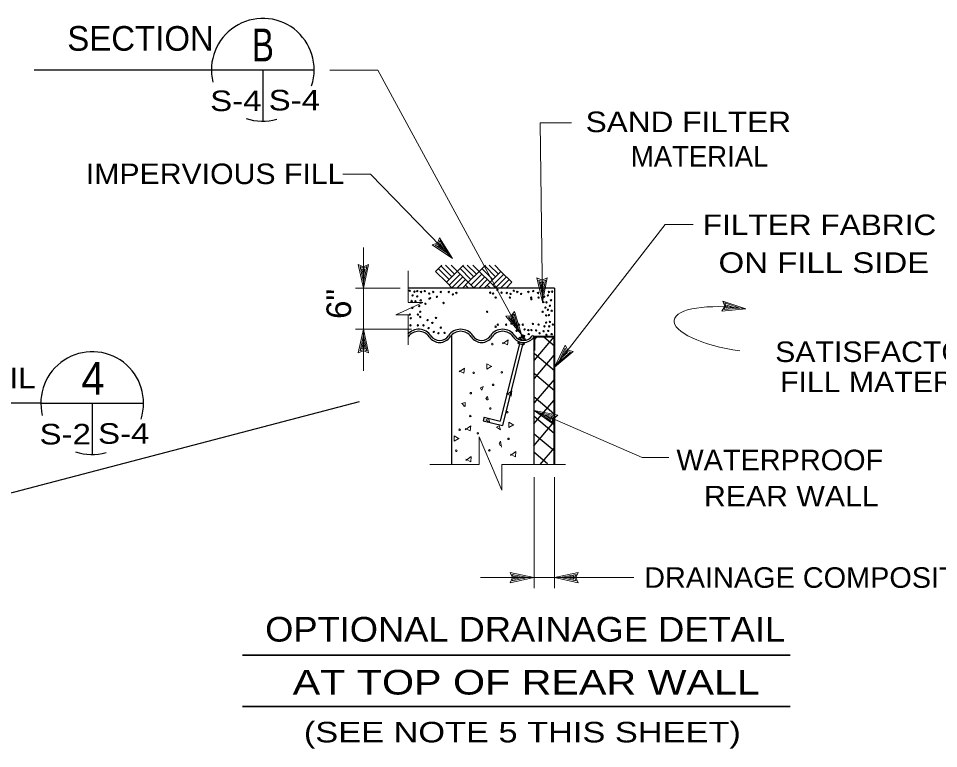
# Model space of a CAD drawing. Extents: x -22.3 to 19.7, y -11.8 to 18.2.
# Drawn here: x -0.15 to 5.45, y -4.4 to 0.04 of the extents above; entities that cross this region are included whole.
import ezdxf
from ezdxf.enums import TextEntityAlignment as Align

# ---------------------------------------------------------------- set-up
doc = ezdxf.new("R2010")
doc.units = 0
doc.header["$LTSCALE"] = 0.05
doc.layers.add('1', color=7, linetype='Continuous', lineweight=13)
doc.layers.add('2', color=7, linetype='Continuous', lineweight=13)

msp = doc.modelspace()

# ---------------------------------------------------------------- linework, layer by layer
at = {"layer": '1'}
for p, q in [((1.74658, -0.26969), (2.03958, -0.26969)), ((2.03958, -0.26969), (2.91358, -1.87769)), ((3.02658, -0.58969), (3.21858, -0.58969)), ((3.02658, -0.58969), (3.04058, -1.67769)), ((1.82558, -0.90269), (1.99558, -0.90269)), ((1.99558, -0.90269), (2.49358, -1.41469)), ((3.78758, -1.20869), (3.11458, -2.07569)), ((3.78758, -1.20869), (3.95858, -1.20869)), ((2.49358, -1.41469), (2.37058, -1.33269)), ((2.38758, -1.33469), (2.40858, -1.32769)), ((2.46758, -1.38769), (2.38758, -1.33469)), ((2.40458, -1.33669), (2.41458, -1.33269)), ((2.44258, -1.36269), (2.40458, -1.33669)), ((2.40858, -1.32769), (2.41658, -1.30669)), ((2.41458, -1.33269), (2.41758, -1.32369)), ((2.49358, -1.41469), (2.41558, -1.28969)), ((2.46758, -1.38769), (2.41658, -1.30669)), ((2.44258, -1.36269), (2.41758, -1.32369)), ((1.95158, -1.59569), (1.92058, -1.45169)), ((1.95158, -1.59569), (1.98258, -1.45169)), ((2.42858, -1.45469), (2.39058, -1.49369)), ((2.45158, -1.45469), (2.50658, -1.50969)), ((2.56158, -1.45469), (2.52258, -1.49369)), ((2.58358, -1.45469), (2.63958, -1.50969)), ((2.61758, -1.45469), (2.65658, -1.49369)), ((2.69458, -1.45469), (2.65658, -1.49369)), ((2.71758, -1.45469), (2.77258, -1.50969)), ((1.95158, -1.55869), (1.93158, -1.46469)), ((1.93158, -1.46469), (1.95158, -1.47369)), ((1.95158, -1.52269), (1.94158, -1.47769)), ((1.94158, -1.47769), (1.95158, -1.48169)), ((1.95158, -1.55869), (1.97158, -1.46469)), ((1.95158, -1.47369), (1.97158, -1.46469)), ((1.95158, -1.52269), (1.96058, -1.47769)), ((1.95158, -1.48169), (1.96058, -1.47769)), ((2.22458, -1.67969), (2.22458, -1.49069)), ((2.39058, -1.49369), (2.45658, -1.55969)), ((2.40658, -1.47669), (2.47358, -1.54269)), ((2.42358, -1.46069), (2.48958, -1.52669)), ((2.52258, -1.49369), (2.45658, -1.55969)), ((2.53958, -1.50969), (2.47358, -1.57669)), ((2.53958, -1.47669), (2.60558, -1.54269)), ((2.55558, -1.46069), (2.62258, -1.52669)), ((2.65658, -1.49369), (2.58958, -1.55969)), ((2.67258, -1.50969), (2.60558, -1.57669)), ((2.65658, -1.49369), (2.72258, -1.55969)), ((2.67258, -1.47669), (2.73858, -1.54269)), ((2.68958, -1.46069), (2.75558, -1.52669)), ((2.78858, -1.49369), (2.72258, -1.55969)), ((2.80558, -1.50969), (2.73858, -1.57669)), ((2.45658, -1.55969), (2.49258, -1.59569)), ((2.55558, -1.52669), (2.48958, -1.59269)), ((2.57258, -1.54269), (2.52058, -1.59569)), ((2.58958, -1.55969), (2.55358, -1.59569)), ((2.58958, -1.55969), (2.62558, -1.59569)), ((2.68958, -1.52669), (2.62258, -1.59269)), ((2.70558, -1.54269), (2.65358, -1.59569)), ((2.72258, -1.55969), (2.68658, -1.59569)), ((2.72258, -1.55969), (2.68658, -1.59569)), ((2.72258, -1.55969), (2.75758, -1.59569)), ((2.82158, -1.52669), (2.75558, -1.59269)), ((2.83858, -1.54269), (2.78658, -1.59569)), ((2.85458, -1.55969), (2.81958, -1.59569)), ((3.04058, -1.67769), (3.00758, -1.53369)), ((3.04058, -1.64069), (3.01858, -1.54669)), ((3.01858, -1.54669), (3.03858, -1.55569)), ((3.03958, -1.60469), (3.02858, -1.55969)), ((3.02858, -1.55969), (3.03958, -1.56369)), ((3.03858, -1.55569), (3.05858, -1.54669)), ((3.03958, -1.60469), (3.04758, -1.55969)), ((3.03958, -1.56369), (3.04758, -1.55969)), ((3.04058, -1.67769), (3.06958, -1.53369)), ((3.04058, -1.64069), (3.05858, -1.54669)), ((2.17458, -1.59569), (1.90358, -1.59569)), ((2.55558, -1.59269), (2.55858, -1.59569)), ((2.57258, -1.57669), (2.59158, -1.59569)), ((2.68958, -1.59269), (2.69158, -1.59569)), ((2.70558, -1.57669), (2.72458, -1.59569)), ((4.27858, -1.72069), (4.13858, -1.67369)), ((2.14858, -1.75669), (2.31358, -1.68169)), ((2.22458, -1.68169), (2.31358, -1.68169)), ((4.27858, -1.72069), (4.13158, -1.73569)), ((4.14658, -1.72569), (4.15758, -1.70669)), ((4.24158, -1.71669), (4.14658, -1.72569)), ((4.24158, -1.71669), (4.15058, -1.68569)), ((4.15758, -1.70669), (4.15058, -1.68569)), ((4.16058, -1.71769), (4.16558, -1.70769)), ((4.20558, -1.71269), (4.16058, -1.71769)), ((4.20558, -1.71269), (4.16258, -1.69869)), ((4.16558, -1.70769), (4.16258, -1.69869)), ((2.14858, -1.75669), (2.22458, -1.75669)), ((2.22458, -1.93969), (2.22458, -1.75669)), ((2.91358, -1.87769), (2.81758, -1.76569)), ((2.83358, -1.77169), (2.85558, -1.77069)), ((2.89558, -1.84469), (2.83358, -1.77169)), ((2.84858, -1.77869), (2.85958, -1.77769)), ((2.87858, -1.81369), (2.84858, -1.77869)), ((2.85558, -1.77069), (2.86858, -1.75269)), ((2.85958, -1.77769), (2.86558, -1.76969)), ((2.87858, -1.81369), (2.86558, -1.76969)), ((2.89558, -1.84469), (2.86858, -1.75269)), ((2.91358, -1.87769), (2.87158, -1.73669)), ((2.24458, -1.84569), (1.90358, -1.84569)), ((1.95158, -1.84569), (1.92058, -1.98969)), ((1.95158, -1.84569), (1.95158, -2.09769)), ((1.95158, -1.84569), (1.98258, -1.98969)), ((1.95158, -1.88269), (1.93158, -1.97669)), ((1.95158, -1.88269), (1.97158, -1.97669)), ((1.95158, -1.91869), (1.94258, -1.96369)), ((1.95158, -1.91869), (1.96158, -1.96369)), ((3.11458, -2.07569), (3.17858, -1.94269)), ((1.95158, -1.96769), (1.93158, -1.97669)), ((1.95158, -1.95969), (1.94258, -1.96369)), ((1.96158, -1.96369), (1.95158, -1.95969)), ((1.97158, -1.97669), (1.95158, -1.96769)), ((3.11458, -2.07569), (3.22758, -1.98069)), ((3.13758, -2.04669), (3.17958, -1.95969)), ((3.13758, -2.04669), (3.21058, -1.98469)), ((3.15958, -2.01769), (3.17858, -1.97669)), ((3.15958, -2.01769), (3.19358, -1.98769)), ((3.17858, -1.97669), (3.18458, -1.98569)), ((3.17958, -1.95969), (3.18958, -1.97969)), ((3.18458, -1.98569), (3.19358, -1.98769)), ((3.18958, -1.97969), (3.21058, -1.98469)), ((3.64658, -2.62469), (2.98958, -2.33869)), ((2.98958, -2.33869), (3.13358, -2.36769)), ((2.98958, -2.33869), (3.10958, -2.42469)), ((3.02358, -2.35369), (3.11758, -2.37269)), ((3.02358, -2.35369), (3.10158, -2.40969)), ((3.05658, -2.36769), (3.09458, -2.39369)), ((3.05658, -2.36769), (3.10158, -2.37669)), ((3.10158, -2.37669), (3.09458, -2.38469)), ((3.09458, -2.38469), (3.09458, -2.39369)), ((3.11758, -2.37269), (3.10158, -2.38769)), ((3.10158, -2.38769), (3.10158, -2.40969)), ((2.65658, -2.66769), (2.65658, -2.49969)), ((2.79358, -2.82469), (2.65658, -2.49969)), ((3.64658, -2.62469), (3.80958, -2.62469)), ((2.65658, -2.66769), (2.35658, -2.66769)), ((2.79358, -2.82469), (2.79358, -2.66769)), ((3.18058, -2.66769), (2.79358, -2.66769)), ((2.98958, -2.74469), (2.98958, -3.41969)), ((3.11458, -2.74469), (3.11458, -3.41969)), ((2.98858, -3.35569), (2.84458, -3.32469)), ((2.98858, -3.35569), (2.84458, -3.38669)), ((2.95158, -3.35569), (2.85758, -3.33569)), ((2.86658, -3.35569), (2.85758, -3.33569)), ((2.95158, -3.35569), (2.85758, -3.37569)), ((2.85758, -3.37569), (2.86658, -3.35569)), ((2.91558, -3.35569), (2.87058, -3.34669)), ((2.87458, -3.35569), (2.87058, -3.34669)), ((2.91558, -3.35569), (2.87058, -3.36569)), ((2.87058, -3.36569), (2.87458, -3.35569)), ((3.11458, -3.35569), (3.25858, -3.32469)), ((3.11458, -3.35569), (3.59658, -3.35569)), ((3.11458, -3.35569), (3.25858, -3.38669)), ((3.15158, -3.35569), (3.24558, -3.33569)), ((3.15158, -3.35569), (3.24558, -3.37569)), ((3.18758, -3.35569), (3.23258, -3.34569)), ((3.18758, -3.35569), (3.23258, -3.36469)), ((3.23258, -3.34569), (3.22858, -3.35569)), ((3.22858, -3.35569), (3.23258, -3.36469)), ((3.24558, -3.33569), (3.23658, -3.35569)), ((3.23658, -3.35569), (3.24558, -3.37569))]:
    msp.add_line(p, q, dxfattribs=at)
at = {"layer": '1', "lineweight": 25}
for p, q in [((3.11458, -1.59569), (2.22458, -1.59569)), ((3.11458, -1.59569), (3.11458, -1.89169)), ((2.48958, -2.66769), (2.48958, -1.88169)), ((2.89958, -1.89369), (2.89758, -1.90369)), ((2.89958, -1.89369), (2.93658, -1.90269)), ((2.90758, -1.89669), (2.90558, -1.90569)), ((2.91358, -1.87769), (2.90958, -1.89669)), ((2.90958, -1.89369), (2.92858, -1.89869)), ((2.91058, -1.89069), (2.92958, -1.89569)), ((2.91158, -1.88369), (2.93058, -1.88869)), ((2.91158, -1.88669), (2.93058, -1.89169)), ((2.91258, -1.87969), (2.93158, -1.88469)), ((2.91358, -1.87769), (2.93258, -1.88269)), ((2.92958, -1.90069), (2.92758, -1.90969)), ((2.93258, -1.88269), (2.92858, -1.90069)), ((2.93658, -1.90269), (2.93458, -1.91269)), ((2.98958, -1.89169), (2.97958, -1.88369)), ((2.98858, -1.91469), (3.00658, -1.89369)), ((2.98958, -2.66769), (2.98958, -1.89169)), ((2.99158, -2.03369), (3.11258, -1.89069)), ((3.11458, -1.94869), (3.04858, -1.89269)), ((2.90058, -1.93269), (2.78458, -2.40469)), ((2.91958, -1.93769), (2.79858, -2.43069)), ((2.89358, -1.91969), (2.89058, -1.93069)), ((2.89058, -1.93069), (2.92758, -1.93969)), ((2.89358, -1.91969), (2.93058, -1.92869)), ((2.89758, -1.90369), (2.93458, -1.91269)), ((2.90058, -1.92169), (2.89758, -1.93169)), ((2.92358, -1.92869), (2.92158, -1.93869)), ((2.93058, -1.92869), (2.92758, -1.93969)), ((2.99158, -2.14569), (3.11258, -2.00269)), ((3.11458, -2.09769), (2.99258, -1.99469)), ((3.11458, -2.21969), (2.99258, -2.11669)), ((2.99258, -2.29369), (3.11358, -2.15069)), ((-0.01042, -2.29469), (-2.00442, -2.29469)), ((3.11058, -2.35969), (2.98858, -2.25669)), ((2.98858, -2.42069), (3.10958, -2.27769)), ((2.68558, -2.38069), (2.68058, -2.40169)), ((2.68058, -2.40169), (2.79858, -2.43069)), ((2.68558, -2.38069), (2.78458, -2.40469)), ((3.11258, -2.47869), (2.99058, -2.37569)), ((2.98858, -2.55369), (3.10958, -2.41069)), ((3.11258, -2.58569), (2.99058, -2.48269)), ((3.02758, -2.66769), (3.11358, -2.56569)), ((3.07258, -2.66469), (2.98858, -2.59369))]:
    msp.add_line(p, q, dxfattribs=at)
at = {"layer": '1', "lineweight": 40}
msp.add_line((3.11458, -2.66769), (3.11458, -1.89169), dxfattribs=at)
at = {"layer": '1', "lineweight": 35}
for p, q in [((1.21658, -3.82769), (4.54758, -3.82769)), ((1.21658, -4.13869), (4.54758, -4.13869))]:
    msp.add_line(p, q, dxfattribs=at)
at = {"layer": '1'}
for points in [[(2.37058, -1.33269), (2.40258, -1.32169), (2.41558, -1.28969)], [(1.95158, -1.84569), (1.95158, -1.59569), (1.95158, -1.34769)], [(1.92058, -1.45169), (1.95158, -1.46569), (1.98258, -1.45169)], [(2.48458, -1.45469), (2.58958, -1.55969), (2.55358, -1.59569)], [(2.75058, -1.45469), (2.78858, -1.49369), (2.85458, -1.55969)], [(3.00758, -1.53369), (3.03858, -1.54769), (3.06958, -1.53369)], [(4.13158, -1.73569), (4.14958, -1.70569), (4.13858, -1.67369)], [(2.81758, -1.76569), (2.85158, -1.76369), (2.87158, -1.73669)], [(3.17858, -1.94269), (3.19458, -1.97269), (3.22758, -1.98069)], [(1.98258, -1.98969), (1.95158, -1.97569), (1.92058, -1.98969)], [(3.13358, -2.36769), (3.10858, -2.39069), (3.10958, -2.42469)], [(3.11458, -3.35569), (2.98858, -3.35569), (2.66358, -3.35569)], [(2.84458, -3.38669), (2.85858, -3.35569), (2.84458, -3.32469)], [(3.25858, -3.32469), (3.24458, -3.35569), (3.25858, -3.38669)]]:
    msp.add_lwpolyline(points, dxfattribs=at)
at = {"layer": '1', "lineweight": 40}
msp.add_lwpolyline([(3.11458, -1.89169), (2.98958, -1.89169), (2.98958, -1.97469)], dxfattribs=at)
at = {"layer": '1', "lineweight": 25}
msp.add_lwpolyline([(1.92558, -2.28769), (-3.54042, -3.71869), (-3.27742, -3.58569)], dxfattribs=at)
at = {"layer": '1'}
for centre in [(2.23408, -1.61169), (2.26208, -1.61669), (2.27908, -1.61369), (2.30208, -1.61869), (2.32508, -1.61369), (2.37608, -1.61869), (2.42208, -1.61869), (2.47108, -1.61869), (2.51708, -1.62469), (2.72208, -1.62269), (2.76708, -1.60569), (2.79208, -1.62269), (2.82408, -1.62469), (2.86608, -1.61169), (2.88808, -1.61869), (2.95508, -1.61869), (2.98508, -1.61369), (3.01408, -1.62469), (3.04208, -1.61169), (3.08008, -1.61869), (3.09908, -1.61669), (2.24508, -1.67369), (2.25108, -1.63969), (2.26808, -1.67569), (2.27908, -1.64569), (2.30008, -1.66969), (2.35208, -1.62869), (2.35308, -1.65869), (2.35708, -1.65669), (2.39908, -1.64769), (2.49608, -1.63369), (2.74008, -1.62869), (2.75608, -1.65269), (2.84308, -1.65269), (2.84708, -1.63069), (2.91108, -1.63069), (2.97208, -1.65269), (2.97408, -1.66269), (3.01708, -1.65269), (3.04608, -1.67969), (3.05208, -1.64769), (3.06508, -1.68169), (3.07408, -1.63969), (3.09308, -1.66869), (2.24908, -1.71569), (2.29108, -1.70469), (2.29708, -1.73869), (2.32908, -1.69069), (2.43908, -1.68569), (2.70408, -1.73869), (3.04208, -1.73869), (3.05908, -1.71369), (3.07408, -1.72669), (3.08608, -1.70269), (3.09708, -1.73269), (2.23408, -1.75569), (2.24008, -1.77869), (2.28308, -1.75569), (2.29708, -1.77069), (2.34208, -1.78969), (2.39308, -1.77669), (3.06308, -1.76169), (3.08008, -1.75969), (2.23808, -1.82169), (2.28308, -1.82169), (2.31708, -1.82169), (2.34808, -1.83869), (2.37108, -1.80669), (2.42208, -1.83569), (2.75608, -1.82969), (2.76908, -1.81769), (2.82008, -1.81769), (2.85208, -1.81069), (2.87708, -1.81069), (2.88308, -1.82969), (2.89808, -1.81769), (2.92108, -1.81769), (2.93208, -1.84669), (2.95508, -1.85069), (2.97408, -1.85069), (2.98308, -1.81269), (3.01708, -1.81669), (3.05308, -1.82769), (3.06308, -1.80469), (3.08208, -1.82769), (3.08608, -1.80069), (3.10508, -1.81669), (2.38008, -1.86169), (2.40808, -1.86969), (2.44508, -1.86769), (2.44508, -1.86769), (2.88308, -1.85569), (2.95708, -1.87469), (3.00208, -1.85269), (3.02308, -1.86969), (3.04808, -1.85769), (3.06508, -1.87869), (3.07608, -1.85569), (3.09708, -1.87469)]:
    msp.add_circle(centre, 0.0043, dxfattribs=at)
at = {"layer": '1', "lineweight": 25}
for centre, radius, start, end in [((2.28833, -1.93481), 0.08947, 34.0772, 138.889), ((2.54333, -1.93481), 0.08947, 34.0772, 145.92281), ((2.79833, -1.93481), 0.08947, 34.0772, 145.92281), ((2.28833, -1.93481), 0.07697, 34.0772, 145.92281), ((2.41583, -1.84856), 0.07697, 214.0772, 325.92281), ((2.41583, -1.84856), 0.06447, 214.0772, 325.92281), ((2.54333, -1.93481), 0.07697, 34.0772, 145.92281), ((2.67083, -1.84856), 0.07697, 214.0772, 325.92281), ((2.67083, -1.84856), 0.06447, 214.0772, 325.92281), ((2.79833, -1.93481), 0.07697, 34.0772, 145.92281), ((2.92583, -1.84856), 0.07697, 214.0772, 325.92281), ((2.92583, -1.84856), 0.06447, 214.0772, 325.92281)]:
    msp.add_arc(centre, radius, start, end, dxfattribs=at)
at = {"layer": '1'}
msp.add_ellipse((4.26058, -1.84869), major_axis=(-0.41882, 0.0589), ratio=0.30562, start_param=4.712389, end_param=7.8539816, dxfattribs=at)
at = {"layer": '2', "lineweight": 25}
for p, q in [((-0.05242, -0.26769), (1.02758, -0.26769)), ((1.02758, -0.26769), (1.65158, -0.26769)), ((1.33958, -0.26769), (1.33958, -0.57969)), ((-0.01042, -2.29469), (0.61358, -2.29469)), ((0.30158, -2.29469), (0.30158, -2.60669))]:
    msp.add_line(p, q, dxfattribs=at)
at = {"layer": '2'}
msp.add_line((2.56658, -2.31469), (2.55158, -2.29769), dxfattribs=at)
for points in [[(2.79858, -1.92569), (2.82858, -1.94069), (2.83158, -1.90969), (2.79858, -1.93369)], [(2.72858, -2.07269), (2.70258, -2.08769), (2.70258, -2.05469), (2.73358, -2.07269)], [(2.53358, -2.09769), (2.56358, -2.11269), (2.56658, -2.08169), (2.53358, -2.10469)], [(2.66958, -2.21569), (2.66458, -2.20069), (2.68058, -2.19369), (2.67258, -2.21569)], [(2.82158, -2.23669), (2.85158, -2.25169), (2.85458, -2.22069), (2.82158, -2.24369)], [(2.54858, -2.29769), (2.57158, -2.29169), (2.57158, -2.31469)], [(2.70758, -2.27669), (2.69558, -2.26669), (2.70758, -2.25369), (2.71058, -2.27369)], [(2.57158, -2.44869), (2.60158, -2.46369), (2.60458, -2.43269), (2.57158, -2.45669)], [(2.86158, -2.42869), (2.83658, -2.44369), (2.83658, -2.41069), (2.86758, -2.42869)], [(2.52858, -2.51169), (2.50358, -2.52669), (2.50358, -2.49369), (2.53358, -2.51169)], [(2.78658, -2.55469), (2.77658, -2.53969), (2.78658, -2.52669), (2.79158, -2.56169)], [(2.57458, -2.63569), (2.60458, -2.65069), (2.60758, -2.61969), (2.57458, -2.64269)], [(2.84658, -2.60569), (2.87658, -2.62069), (2.87958, -2.58969), (2.84658, -2.61269)]]:
    msp.add_lwpolyline(points, dxfattribs=at)
for points in [[(2.72158, -2.41169), (2.69558, -2.39669), (2.71358, -2.38769)], [(2.78658, -2.45669), (2.76058, -2.44169), (2.77858, -2.43269)]]:
    msp.add_lwpolyline(points, close=True, dxfattribs=at)
for centre in [(2.73546, -1.93569), (2.62221, -2.11044), (2.79396, -2.10744), (2.74071, -2.18319), (2.60496, -2.23419), (2.72346, -2.32719), (2.82696, -2.34969), (2.60196, -2.37294), (2.53671, -2.45619), (2.64771, -2.47869), (2.83446, -2.51169), (2.51646, -2.58444), (2.71821, -2.58219)]:
    msp.add_circle(centre, 0.00487, dxfattribs=at)
at = {"layer": '2', "lineweight": 25}
for centre, start, end in [((1.33958, -0.26769), 341.96976, 193.81208), ((1.33958, -0.26769), 251.04049, 285.74671), ((0.30158, -2.29469), 341.96976, 193.81208), ((0.30158, -2.29469), 251.04049, 285.74671)]:
    msp.add_arc(centre, 0.3125, start, end, dxfattribs=at)

# ---------------------------------------------------------------- texts
at = {"layer": '1'}
msp.add_text('SECTION', height=0.15, dxfattribs=at).set_placement((1.04158, -0.15169), align=Align.RIGHT)
for s, width, p in [('SAND FILTER', 1.15, (3.30358, -0.64669)), ('DRAINAGE COMPOSITE', 1.05, (3.65958, -3.41769))]:
    msp.add_text(s, height=0.125, dxfattribs=dict(at, width=width)).set_placement(p)
msp.add_text('MATERIAL', height=0.125, dxfattribs=at).set_placement((3.99708, -0.85669), align=Align.CENTER)
for s, height, width, p in [('IMPERVIOUS FILL', 0.125, 1.1, (1.04958, -0.96269)), ('FILTER FABRIC', 0.125, 1.15, (4.72658, -1.27269)), ('ON FILL SIDE', 0.125, 1.2, (4.75308, -1.50269)), ('SATISFACTORY', 0.125, 1.1, (5.16158, -2.04469)), ('FILL MATERIAL', 0.125, 1.1, (5.15558, -2.22769)), ('WATERPROOF', 0.125, 1.05, (4.48508, -2.70269)), ('REAR WALL', 0.125, 1.1, (4.55508, -2.92269)), ('OPTIONAL DRAINAGE DETAIL', 0.15, 1.1, (2.93558, -3.74469)), ('AT TOP OF REAR WALL', 0.15, 1.25, (2.94258, -4.06669)), ('(SEE NOTE 5 THIS SHEET)', 0.125, 1.25, (2.91858, -4.35769))]:
    msp.add_text(s, height=height, dxfattribs=dict(at, width=width)).set_placement(p, align=Align.CENTER)
msp.add_text('6"', height=0.15, rotation=90, dxfattribs=at).set_placement((1.87658, -1.69119), align=Align.CENTER)
at = {"layer": '1', "width": 1.15}
msp.add_text('VENTILATOR DETAIL', height=0.125, dxfattribs=at).set_placement((-0.04142, -2.20369), align=Align.RIGHT)
at = {"layer": '2'}
for s, height, width, p in [('B', 0.2, 0.75, (1.34008, -0.21669)), ('S-4', 0.125, 1.2, (1.17558, -0.51869)), ('S-4', 0.125, 1.2, (1.53158, -0.51469)), ('4', 0.2, 0.95, (0.30658, -2.24369)), ('S-2', 0.125, 1.2, (0.13758, -2.54569)), ('S-4', 0.125, 1.2, (0.49358, -2.54169))]:
    msp.add_text(s, height=height, dxfattribs=dict(at, width=width)).set_placement(p, align=Align.CENTER)

doc.saveas('drawing.dxf')
